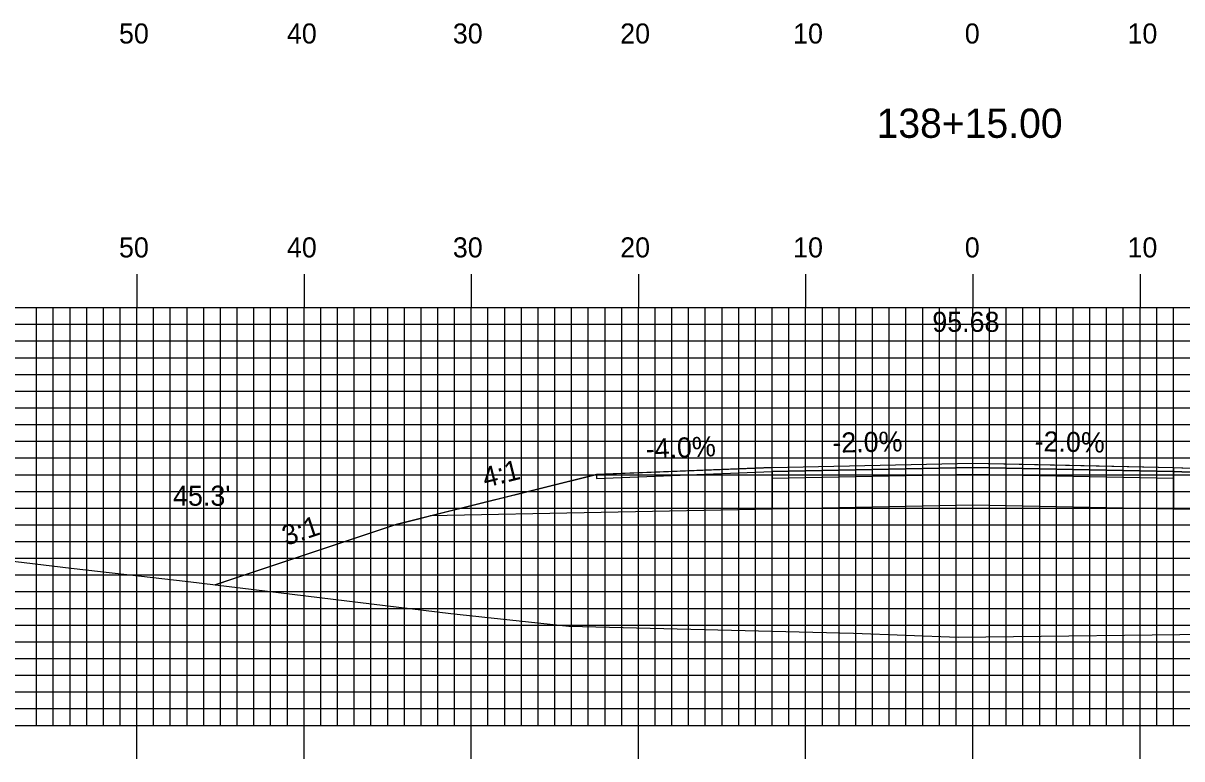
# Model space of a CAD drawing. Extents: x 1775564 to 1775907, y 442591 to 442811.
# Drawn here: x 1775672.9 to 1775742.2, y 442686.7 to 442730.7 of the extents above; entities that cross this region are included whole.
import ezdxf

# ---------------------------------------------------------------- set-up
doc = ezdxf.new("R2010")
doc.units = 0
for name, color, linetype in [('ANNOTATION', 7, 'Continuous'), ('D_Roadway_Centerline', 7, 'Continuous'), ('D_Roadway_Centerline_Text', 7, 'Continuous'), ('D_Roadway_Edge_Shoulder', 7, 'Continuous'), ('D_Roadway_Edge_TW', 7, 'Continuous'), ('D_Roadway_Pavement', 7, 'Continuous'), ('D_Roadway_SlopeLines', 7, 'Continuous'), ('D_Roadway_SubGrade', 7, 'Continuous'), ('D_Text_Standard', 7, 'Continuous'), ('H_V ANNOTATION', 7, 'Continuous'), ('MAJOR', 7, 'Continuous'), ('MINOR', 7, 'Continuous'), ('S_Roadway_Centerline', 7, 'Continuous')]:
    doc.layers.add(name, color=color, linetype=linetype)

msp = doc.modelspace()

# ---------------------------------------------------------------- linework, layer by layer
at = {"layer": 'D_Roadway_Centerline'}
msp.add_lwpolyline([(1775684.386, 442697.075), (1775685.386, 442697.409), (1775695.208, 442700.682), (1775695.211, 442700.683), (1775696.501, 442701.006), (1775697.254, 442701.194), (1775697.256, 442701.195), (1775706.778, 442703.575), (1775707.21, 442703.683), (1775707.359, 442703.689), (1775717.712, 442704.104), (1775717.718, 442704.104), (1775729.712, 442704.344), (1775729.714, 442704.344), (1775734.598, 442704.246), (1775741.712, 442704.104), (1775741.714, 442704.104), (1775744.529, 442703.992)], dxfattribs=at)
at = {"layer": 'D_Roadway_Edge_Shoulder'}
for points in [[(1775717.711, 442704.104), (1775707.21, 442703.683), (1775707.21, 442703.433), (1775717.711, 442703.854)], [(1775741.712, 442704.104), (1775749.711, 442703.784), (1775749.711, 442703.784), (1775752.712, 442703.664), (1775752.712, 442703.414), (1775741.712, 442703.854)]]:
    msp.add_lwpolyline(points, close=True, dxfattribs=at)
at = {"layer": 'D_Roadway_Edge_TW'}
msp.add_lwpolyline([(1775717.711, 442703.854), (1775717.711, 442704.104), (1775729.712, 442704.344), (1775741.712, 442704.104), (1775741.712, 442703.854), (1775729.712, 442704.094)], close=True, dxfattribs=at)
at = {"layer": 'D_Roadway_Pavement'}
msp.add_lwpolyline([(1775717.711, 442703.437), (1775717.711, 442703.854), (1775729.712, 442704.094), (1775741.712, 442703.854), (1775741.712, 442703.437), (1775729.712, 442703.677)], close=True, dxfattribs=at)
at = {"layer": 'D_Roadway_SlopeLines'}
msp.add_lwpolyline([(1775707.21, 442703.683), (1775695.211, 442700.683), (1775684.386, 442697.075)], dxfattribs=at)
at = {"layer": 'D_Roadway_SubGrade'}
for points in [[(1775717.711, 442701.604), (1775697.254, 442701.194), (1775707.21, 442703.683), (1775707.21, 442703.433), (1775717.711, 442703.854)], [(1775717.711, 442701.604), (1775717.711, 442703.854), (1775729.712, 442704.094), (1775741.712, 442703.854), (1775741.712, 442701.604), (1775729.712, 442701.844)], [(1775741.712, 442703.854), (1775752.712, 442703.414), (1775752.712, 442703.664), (1775759.988, 442701.238), (1775741.712, 442701.604)]]:
    msp.add_lwpolyline(points, close=True, dxfattribs=at)
at = {"layer": 'MAJOR'}
for p, q in [((1775679.711, 442715.669), (1775679.711, 442713.665)), ((1775689.711, 442715.669), (1775689.711, 442713.665)), ((1775699.711, 442715.669), (1775699.711, 442713.665)), ((1775709.711, 442715.669), (1775709.711, 442713.665)), ((1775719.711, 442715.669), (1775719.711, 442713.665)), ((1775729.711, 442715.669), (1775729.711, 442713.665)), ((1775739.711, 442715.669), (1775739.711, 442713.665)), ((1775589.711, 442713.665), (1775869.711, 442713.665)), ((1775589.711, 442713.665), (1775869.711, 442713.665)), ((1775679.711, 442688.665), (1775679.711, 442713.665)), ((1775689.711, 442688.665), (1775689.711, 442713.665)), ((1775699.711, 442688.665), (1775699.711, 442713.665)), ((1775709.711, 442688.665), (1775709.711, 442713.665)), ((1775719.711, 442688.665), (1775719.711, 442713.665)), ((1775729.711, 442688.665), (1775729.711, 442713.665)), ((1775739.711, 442688.665), (1775739.711, 442713.665)), ((1775589.711, 442708.665), (1775869.711, 442708.665)), ((1775589.711, 442703.665), (1775869.711, 442703.665)), ((1775589.711, 442698.665), (1775869.711, 442698.665)), ((1775589.711, 442693.665), (1775869.711, 442693.665)), ((1775589.711, 442688.665), (1775869.711, 442688.665)), ((1775589.711, 442688.665), (1775869.711, 442688.665)), ((1775679.711, 442686.661), (1775679.711, 442688.665)), ((1775689.711, 442686.661), (1775689.711, 442688.665)), ((1775699.711, 442686.661), (1775699.711, 442688.665)), ((1775709.711, 442686.661), (1775709.711, 442688.665)), ((1775719.711, 442686.661), (1775719.711, 442688.665)), ((1775729.711, 442686.661), (1775729.711, 442688.665)), ((1775739.711, 442686.661), (1775739.711, 442688.665))]:
    msp.add_line(p, q, dxfattribs=at)
at = {"layer": 'MINOR'}
for p, q in [((1775673.711, 442688.665), (1775673.711, 442713.665)), ((1775674.711, 442688.665), (1775674.711, 442713.665)), ((1775675.711, 442688.665), (1775675.711, 442713.665)), ((1775676.711, 442688.665), (1775676.711, 442713.665)), ((1775677.711, 442688.665), (1775677.711, 442713.665)), ((1775678.711, 442688.665), (1775678.711, 442713.665)), ((1775680.711, 442688.665), (1775680.711, 442713.665)), ((1775681.711, 442688.665), (1775681.711, 442713.665)), ((1775682.711, 442688.665), (1775682.711, 442713.665)), ((1775683.711, 442688.665), (1775683.711, 442713.665)), ((1775684.711, 442688.665), (1775684.711, 442713.665)), ((1775685.711, 442688.665), (1775685.711, 442713.665)), ((1775686.711, 442688.665), (1775686.711, 442713.665)), ((1775687.711, 442688.665), (1775687.711, 442713.665)), ((1775688.711, 442688.665), (1775688.711, 442713.665)), ((1775690.711, 442688.665), (1775690.711, 442713.665)), ((1775691.711, 442688.665), (1775691.711, 442713.665)), ((1775692.711, 442688.665), (1775692.711, 442713.665)), ((1775693.711, 442688.665), (1775693.711, 442713.665)), ((1775694.711, 442688.665), (1775694.711, 442713.665)), ((1775695.711, 442688.665), (1775695.711, 442713.665)), ((1775696.711, 442688.665), (1775696.711, 442713.665)), ((1775697.711, 442688.665), (1775697.711, 442713.665)), ((1775698.711, 442688.665), (1775698.711, 442713.665)), ((1775700.711, 442688.665), (1775700.711, 442713.665)), ((1775701.711, 442688.665), (1775701.711, 442713.665)), ((1775702.711, 442688.665), (1775702.711, 442713.665)), ((1775703.711, 442688.665), (1775703.711, 442713.665)), ((1775704.711, 442688.665), (1775704.711, 442713.665)), ((1775705.711, 442688.665), (1775705.711, 442713.665)), ((1775706.711, 442688.665), (1775706.711, 442713.665)), ((1775707.711, 442688.665), (1775707.711, 442713.665)), ((1775708.711, 442688.665), (1775708.711, 442713.665)), ((1775710.711, 442688.665), (1775710.711, 442713.665)), ((1775711.711, 442688.665), (1775711.711, 442713.665)), ((1775712.711, 442688.665), (1775712.711, 442713.665)), ((1775713.711, 442688.665), (1775713.711, 442713.665)), ((1775714.711, 442688.665), (1775714.711, 442713.665)), ((1775715.711, 442688.665), (1775715.711, 442713.665)), ((1775716.711, 442688.665), (1775716.711, 442713.665)), ((1775717.711, 442688.665), (1775717.711, 442713.665)), ((1775718.711, 442688.665), (1775718.711, 442713.665)), ((1775720.711, 442688.665), (1775720.711, 442713.665)), ((1775721.711, 442688.665), (1775721.711, 442713.665)), ((1775722.711, 442688.665), (1775722.711, 442713.665)), ((1775723.711, 442688.665), (1775723.711, 442713.665)), ((1775724.711, 442688.665), (1775724.711, 442713.665)), ((1775725.711, 442688.665), (1775725.711, 442713.665)), ((1775726.711, 442688.665), (1775726.711, 442713.665)), ((1775727.711, 442688.665), (1775727.711, 442713.665)), ((1775728.711, 442688.665), (1775728.711, 442713.665)), ((1775730.711, 442688.665), (1775730.711, 442713.665)), ((1775731.711, 442688.665), (1775731.711, 442713.665)), ((1775732.711, 442688.665), (1775732.711, 442713.665)), ((1775733.711, 442688.665), (1775733.711, 442713.665)), ((1775734.711, 442688.665), (1775734.711, 442713.665)), ((1775735.711, 442688.665), (1775735.711, 442713.665)), ((1775736.711, 442688.665), (1775736.711, 442713.665)), ((1775737.711, 442688.665), (1775737.711, 442713.665)), ((1775738.711, 442688.665), (1775738.711, 442713.665)), ((1775740.711, 442688.665), (1775740.711, 442713.665)), ((1775741.711, 442688.665), (1775741.711, 442713.665)), ((1775589.711, 442712.665), (1775869.711, 442712.665)), ((1775589.711, 442711.665), (1775869.711, 442711.665)), ((1775589.711, 442710.665), (1775869.711, 442710.665)), ((1775589.711, 442709.665), (1775869.711, 442709.665)), ((1775589.711, 442707.665), (1775869.711, 442707.665)), ((1775589.711, 442706.665), (1775869.711, 442706.665)), ((1775589.711, 442705.665), (1775869.711, 442705.665)), ((1775589.711, 442704.665), (1775869.711, 442704.665)), ((1775589.711, 442702.665), (1775869.711, 442702.665)), ((1775589.711, 442701.665), (1775869.711, 442701.665)), ((1775589.711, 442700.665), (1775869.711, 442700.665)), ((1775589.711, 442699.665), (1775869.711, 442699.665)), ((1775589.711, 442697.665), (1775869.711, 442697.665)), ((1775589.711, 442696.665), (1775869.711, 442696.665)), ((1775589.711, 442695.665), (1775869.711, 442695.665)), ((1775589.711, 442694.665), (1775869.711, 442694.665)), ((1775589.711, 442692.665), (1775869.711, 442692.665)), ((1775589.711, 442691.665), (1775869.711, 442691.665)), ((1775589.711, 442690.665), (1775869.711, 442690.665)), ((1775589.711, 442689.665), (1775869.711, 442689.665))]:
    msp.add_line(p, q, dxfattribs=at)
at = {"layer": 'S_Roadway_Centerline'}
msp.add_lwpolyline([(1775657.728, 442700.236), (1775675.773, 442698.079), (1775679.104, 442697.689), (1775682.768, 442697.273), (1775698.488, 442695.352), (1775705.547, 442694.605), (1775722.571, 442694.19), (1775728.833, 442693.949), (1775745.404, 442694.138), (1775753.291, 442694.36), (1775767.434, 442694.511), (1775771.774, 442694.475), (1775776.187, 442694.581), (1775784.104, 442695.04), (1775791.385, 442695.382)], dxfattribs=at)

# ---------------------------------------------------------------- texts
at = {"layer": 'ANNOTATION'}
for s, rotation, p in [('-4.0%', 2.29578, (1775710.167, 442704.603)), ('-2.0%', 1.1458, (1775721.321, 442704.977)), ('-2.0%', 358.85426, (1775733.399, 442705.071)), ('4:1', 14.03627, (1775700.552, 442702.88)), ('3:1', 18.43293, (1775688.636, 442699.4))]:
    msp.add_text(s, height=1.2, rotation=rotation, dxfattribs=at).set_placement(p)
at = {"layer": 'D_Roadway_Centerline'}
for s, p in [('C', (1775729.706, 442704.344)), ('L', (1775729.712, 442704.337))]:
    msp.add_text(s, height=0.0146, dxfattribs=at).set_placement(p)
at = {"layer": 'D_Roadway_Centerline_Text'}
msp.add_text('95.68', height=1.2, dxfattribs=at).set_placement((1775727.287, 442712.21))
at = {"layer": 'D_Text_Standard'}
msp.add_text("45.3'", height=1.2, dxfattribs=at).set_placement((1775681.876, 442701.807))
at = {"layer": 'H_V ANNOTATION'}
for s, height, p in [('50', 1.2, (1775678.641, 442729.465)), ('40', 1.2, (1775688.684, 442729.465)), ('30', 1.2, (1775698.609, 442729.465)), ('20', 1.2, (1775708.619, 442729.465)), ('10', 1.2, (1775718.962, 442729.465)), ('0', 1.2, (1775729.23, 442729.465)), ('10', 1.2, (1775738.962, 442729.465)), ('138+15.00', 1.75, (1775723.953, 442723.821)), ('50', 1.2, (1775678.641, 442716.665)), ('40', 1.2, (1775688.684, 442716.665)), ('30', 1.2, (1775698.609, 442716.665)), ('20', 1.2, (1775708.619, 442716.665)), ('10', 1.2, (1775718.962, 442716.665)), ('0', 1.2, (1775729.23, 442716.665)), ('10', 1.2, (1775738.962, 442716.665))]:
    msp.add_text(s, height=height, dxfattribs=at).set_placement(p)

doc.saveas('drawing.dxf')
